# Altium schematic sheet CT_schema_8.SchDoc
size 277 x 170 mm
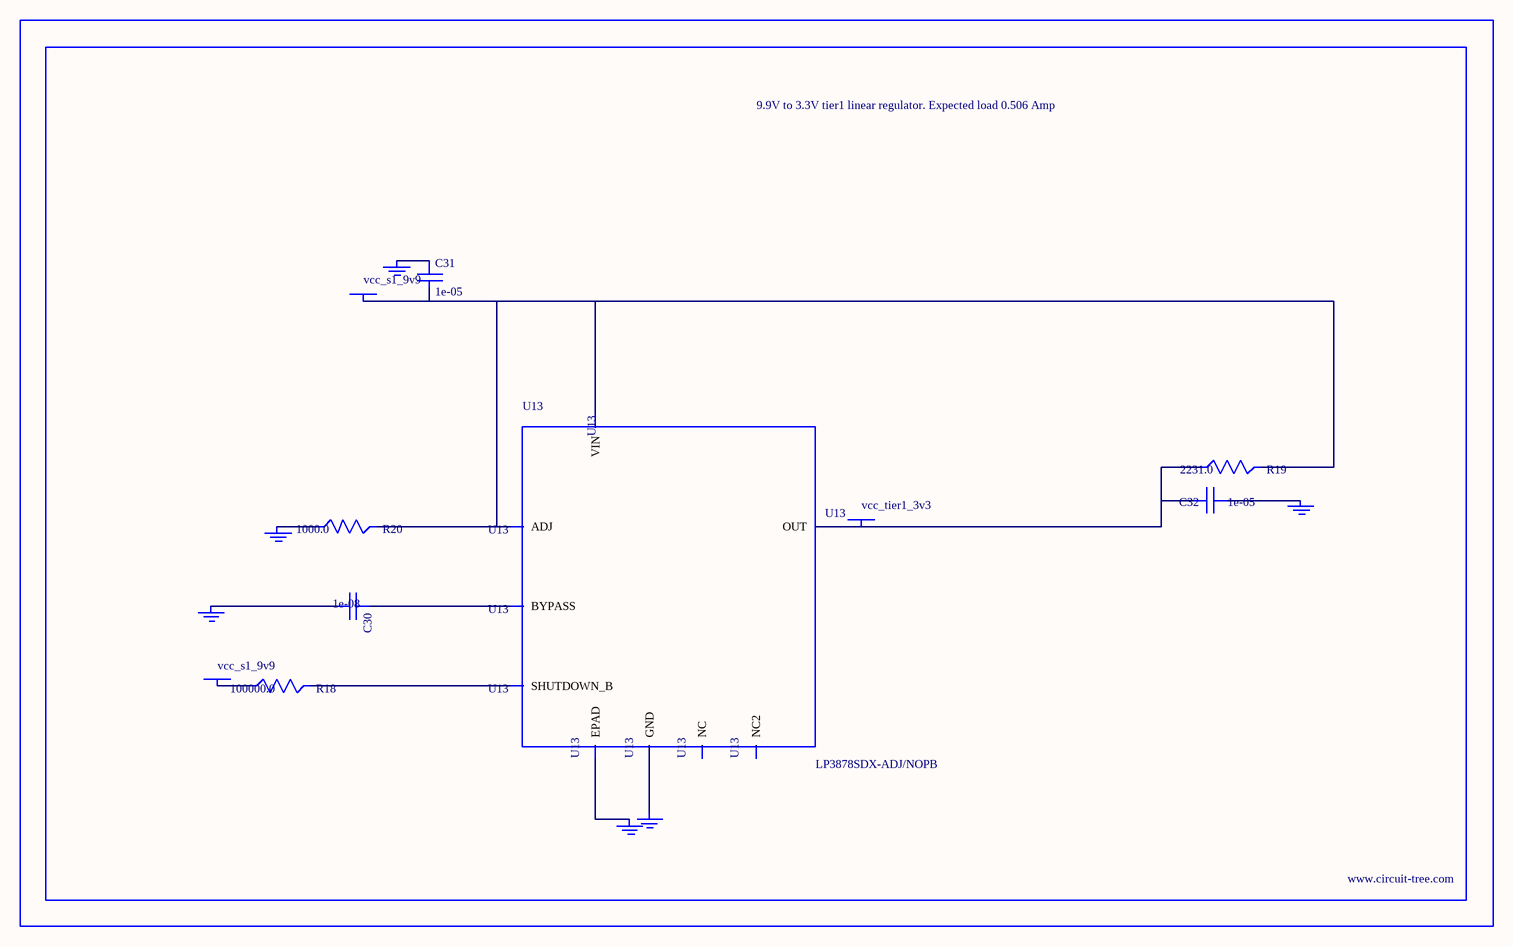
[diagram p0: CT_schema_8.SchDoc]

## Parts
BORDER7  (no value)
C30  1e-08  [C0402]
C31  1e-05  [C1206]
C32  1e-05  [C1210]
GND_INSTANCE_7_0  (no value)
GND_INSTANCE_7_1  (no value)
GND_INSTANCE_7_2  (no value)
GND_INSTANCE_7_3  (no value)
GND_INSTANCE_7_4  (no value)
GND_INSTANCE_7_5  (no value)
POWER_INSTANCE_7_0  vcc_s1_9v9
POWER_INSTANCE_7_1  vcc_s1_9v9
POWER_INSTANCE_7_2  vcc_tier1_3v3
R18  100000.0  [R0603]
R19  2231.0  [R0603]
R20  1000.0  [R0603]
U13  LP3878SDX-ADJ/NOPB  [WSON-8]

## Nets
NetC30_1: C30.1 U13.1(BYPASS)
NetC30_2: C30.2 GND_INSTANCE_7_0.0(GND)
NetC31_1: C31.1 GND_INSTANCE_7_1.0(GND)
NetC31_2: C31.2 POWER_INSTANCE_7_0.0(PWR) R19.2 R20.2 U13.4(VIN) U13.6(ADJ)
NetC32_1: C32.1 GND_INSTANCE_7_2.0(GND)
NetC32_2: C32.2 POWER_INSTANCE_7_2.0(PWR) R19.1 U13.5(OUT)
NetGND_INSTANCE_7_3_0: GND_INSTANCE_7_3.0(GND) R20.1
NetGND_INSTANCE_7_4_0: GND_INSTANCE_7_4.0(GND) U13.PAD(EPAD)
NetGND_INSTANCE_7_5_0: GND_INSTANCE_7_5.0(GND) U13.3(GND)
NetPOWER_INSTANCE_7_1_0: POWER_INSTANCE_7_1.0(PWR) R18.1
NetR18_2: R18.2 U13.8(SHUTDOWN_B)

Not connected (* = marked no-connect by the designer): U13 2(NC) 7(NC2)

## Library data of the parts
BORDER7 = BORDER_PAGE7
C30 = C0402C103K3RAC
C31 = C1206C106K3RACTU
C32 = GRM32DR61E106MA12L
GND_INSTANCE_7_0-GND_INSTANCE_7_5 = GND
POWER_INSTANCE_7_0-POWER_INSTANCE_7_2 = PWR
R18 = RC0603JR-07100KL
R19 = R19
R20 = RC0603JR-071KL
